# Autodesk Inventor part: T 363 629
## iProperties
Created: 2006-07
Part Number: T 363 629
Material: 1.0330
Document SubType Name: Sheet Metal
Designer: I.Baliuc
Description: Blendengrundplatte
Density: 7.84 g/cm^3
Sheet Metal Rule: Default
Title: Blendengrundplatte
Company: Mayer & Mueller Schaltgeräte AG
Zweck: für Vorkontakt HSLT
Abmessung: Bl. 4mm
Author: T.Messerschmitt
Revision Number: 363629
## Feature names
1. Bohrung_M6 [Hole]
2. Bohrung_Senk [Hole]
3. Bohrung_Ø6.2 [Hole]
4. Bohrung_M5 [Hole]
5. Grobblech1
6. Grobblech2
7. Biegung1
8. Grobblech4
9. Biegung3
